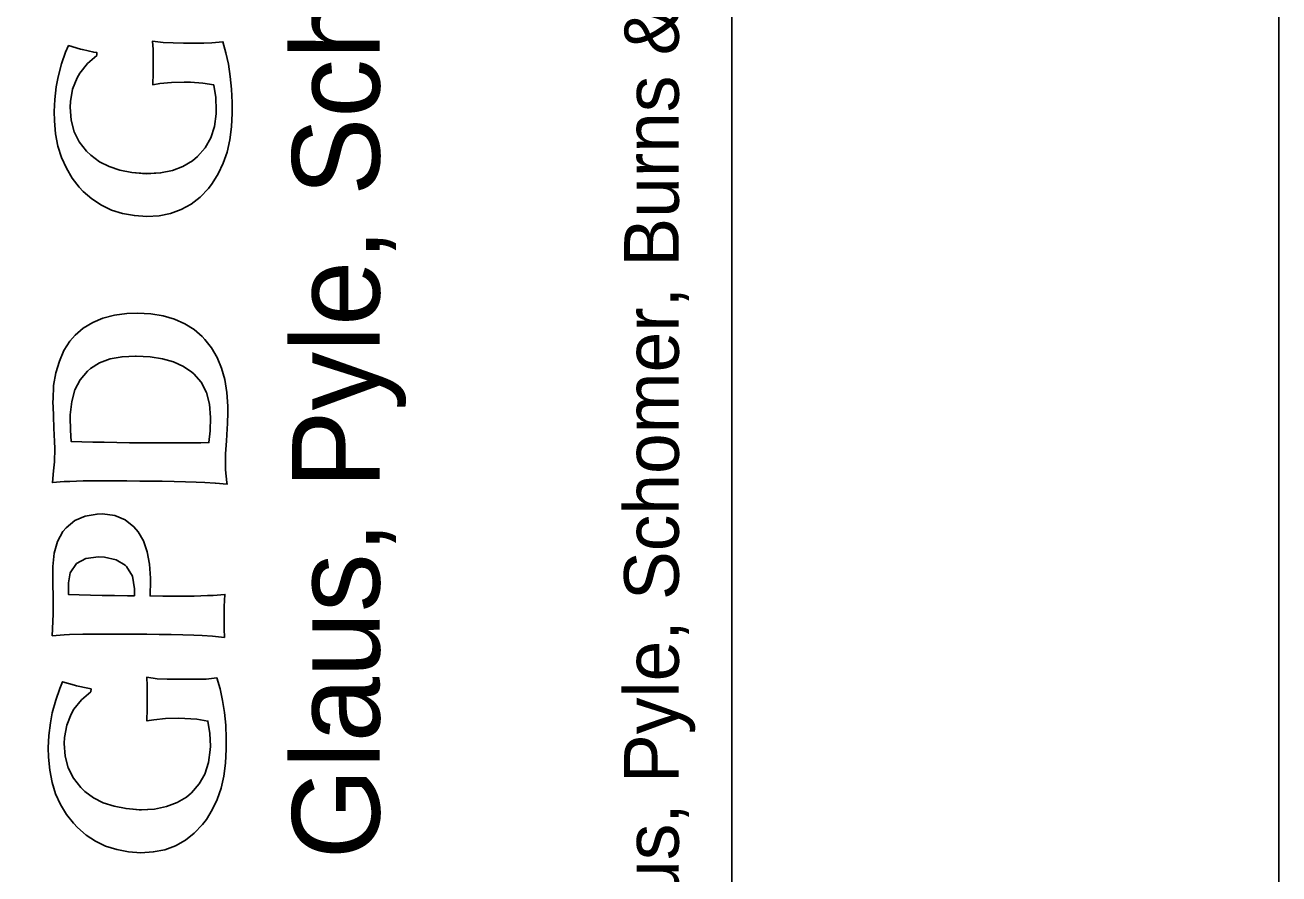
# Model space of a CAD drawing. Extents: x 0 to 34, y 0 to 22.
# Drawn here: x 32.854 to 34, y 19.23 to 20.006 of the extents above; entities that cross this region are included whole.
import ezdxf

# ---------------------------------------------------------------- set-up
doc = ezdxf.new("R2010")
doc.units = 0
for name, color, linetype in [('SH_Border', 7, 'Continuous'), ('SH_Cut_Line', 7, 'Continuous'), ('SH_Data', 7, 'Continuous')]:
    doc.layers.add(name, color=color, linetype=linetype)

msp = doc.modelspace()

# ---------------------------------------------------------------- linework, layer by layer
at = {"layer": 'SH_Border'}
msp.add_lwpolyline([(2, 21.5), (33.5, 21.5), (33.5, 0.5), (2, 0.5)], close=True, dxfattribs=at)
at = {"layer": 'SH_Cut_Line'}
msp.add_lwpolyline([(0, 22), (34, 22), (34, 0), (0, 0)], close=True, dxfattribs=at)
at = {"layer": 'SH_Data'}
for points in [[(32.9515, 19.871), (32.9405, 19.8731), (32.9306, 19.8765), (32.9217, 19.8809), (32.9138, 19.8868), (32.9099, 19.8904), (32.9032, 19.8989), (32.8985, 19.9083), (32.8958, 19.919), (32.895, 19.9306), (32.8952, 19.936), (32.8972, 19.9473), (32.9013, 19.9575), (32.9038, 19.9619), (32.9107, 19.9705), (32.9194, 19.978), (32.9194, 19.9806), (32.9165, 19.981), (32.9062, 19.9833), (32.9043, 19.9839), (32.8935, 19.987), (32.8908, 19.981), (32.8871, 19.9703), (32.884, 19.9585), (32.8823, 19.9493), (32.8809, 19.9378), (32.8804, 19.9268), (32.8806, 19.9181), (32.8816, 19.9063), (32.8838, 19.895), (32.8871, 19.8846), (32.8915, 19.8749), (32.8969, 19.8659), (32.9033, 19.8576), (32.907, 19.8536), (32.9149, 19.8468), (32.9235, 19.8411), (32.9328, 19.8367), (32.9429, 19.8335), (32.9537, 19.8316), (32.9651, 19.8309), (32.9764, 19.8315), (32.9868, 19.8336), (32.9966, 19.8371), (33.0056, 19.8421), (33.0138, 19.8486), (33.0213, 19.8565), (33.0248, 19.8611), (33.0303, 19.8698), (33.0348, 19.8795), (33.0384, 19.8897), (33.0409, 19.9008), (33.0425, 19.9127), (33.0431, 19.9253), (33.043, 19.9351), (33.0425, 19.9472), (33.0413, 19.9589), (33.0397, 19.9699), (33.0374, 19.9805), (33.0346, 19.9906), (33.0246, 19.9894), (33.0172, 19.9892), (33.0042, 19.9892), (32.9985, 19.9892), (32.9891, 19.9894), (32.98, 19.9898), (32.9703, 19.9912), (32.9708, 19.9833), (32.9709, 19.9711), (32.9708, 19.9622), (32.9705, 19.9512), (32.9769, 19.9523), (32.9876, 19.9534), (32.9991, 19.9537), (33.0051, 19.9535), (33.0162, 19.9527), (33.0263, 19.9511), (33.0263, 19.9508), (33.028, 19.9397), (33.0286, 19.928), (33.0285, 19.9247), (33.0269, 19.913), (33.0235, 19.9027), (33.0184, 19.8935), (33.0114, 19.8855), (33.0067, 19.8816), (32.9981, 19.8765), (32.9884, 19.8728), (32.9776, 19.8706), (32.9644, 19.8699), (32.9515, 19.871)], [(33.0303, 19.8698), (33.0348, 19.8795), (33.0384, 19.8897), (33.0409, 19.9008), (33.0425, 19.9127), (33.0431, 19.9253), (33.043, 19.9351), (33.0425, 19.9472), (33.0413, 19.9589), (33.0397, 19.9699), (33.0374, 19.9805), (33.0346, 19.9906), (33.0246, 19.9894), (33.0172, 19.9892), (33.0042, 19.9892), (32.9985, 19.9892), (32.9891, 19.9894), (32.98, 19.9898), (32.9703, 19.9912)], [(32.9703, 19.9912), (32.9708, 19.9833), (32.9709, 19.9711)], [(32.8935, 19.987), (32.8908, 19.981), (32.8871, 19.9703), (32.884, 19.9585), (32.8823, 19.9493), (32.8809, 19.9378), (32.8804, 19.9268)], [(32.895, 19.9306), (32.8952, 19.936), (32.8972, 19.9473), (32.9013, 19.9575), (32.9038, 19.9619), (32.9107, 19.9705), (32.9194, 19.978), (32.9194, 19.9806), (32.9165, 19.981), (32.9062, 19.9833), (32.9043, 19.9839), (32.8935, 19.987)], [(32.895, 19.9306), (32.8952, 19.936), (32.8972, 19.9473), (32.9013, 19.9575), (32.9038, 19.9619), (32.9107, 19.9705), (32.9194, 19.978), (32.9194, 19.9806), (32.9165, 19.981), (32.9062, 19.9833), (32.9043, 19.9839), (32.8935, 19.987)], [(32.9709, 19.9711), (32.9708, 19.9622), (32.9705, 19.9512)], [(32.9705, 19.9512), (32.9769, 19.9523)], [(32.9769, 19.9523), (32.9876, 19.9534), (32.9991, 19.9537), (33.0051, 19.9535), (33.0162, 19.9527), (33.0263, 19.9511), (33.0263, 19.9508), (33.028, 19.9397), (33.0286, 19.928)], [(32.8804, 19.9268), (32.8806, 19.9181), (32.8816, 19.9063), (32.8838, 19.895), (32.8871, 19.8846), (32.8915, 19.8749), (32.8969, 19.8659), (32.9033, 19.8576), (32.907, 19.8536), (32.9149, 19.8468), (32.9235, 19.8411), (32.9328, 19.8367), (32.9429, 19.8335), (32.9537, 19.8316), (32.9651, 19.8309), (32.9764, 19.8315), (32.9868, 19.8336), (32.9966, 19.8371), (33.0056, 19.8421), (33.0138, 19.8486), (33.0213, 19.8565), (33.0248, 19.8611), (33.0303, 19.8698)], [(33.0286, 19.928), (33.0285, 19.9247), (33.0269, 19.913), (33.0235, 19.9027), (33.0184, 19.8935), (33.0114, 19.8855), (33.0067, 19.8816), (32.9981, 19.8765), (32.9884, 19.8728), (32.9776, 19.8706), (32.9656, 19.87), (32.9634, 19.87), (32.9515, 19.871), (32.9405, 19.8731), (32.9306, 19.8765), (32.9217, 19.8809), (32.9138, 19.8868), (32.9099, 19.8904), (32.9032, 19.8989), (32.8985, 19.9083), (32.8958, 19.919), (32.895, 19.9306)], [(32.9904, 19.737), (32.98, 19.7399), (32.9687, 19.7418), (32.9566, 19.7425), (32.9468, 19.7421), (32.9354, 19.7406), (32.925, 19.7379), (32.9156, 19.7339), (32.907, 19.7288), (32.8996, 19.7224), (32.8948, 19.7168), (32.8893, 19.7082), (32.8851, 19.6987), (32.8819, 19.6879), (32.8799, 19.6762), (32.8793, 19.6634), (32.8792, 19.6621), (32.8796, 19.6494), (32.8797, 19.6483), (32.8802, 19.6372), (32.8808, 19.6252), (32.8809, 19.6186), (32.8806, 19.6065), (32.8799, 19.5983), (32.8787, 19.5876), (32.8895, 19.5885), (32.8946, 19.5887), (32.9069, 19.5891), (32.9144, 19.5891), (32.9246, 19.5892), (32.9354, 19.5891), (32.9468, 19.5891), (32.9587, 19.589), (32.9676, 19.5889), (32.979, 19.5888), (32.99, 19.5886), (33.0005, 19.5883), (33.0103, 19.5881), (33.0181, 19.5877), (33.0275, 19.5872), (33.0277, 19.5872), (33.0385, 19.5861), (33.0382, 19.5877), (33.037, 19.5993), (33.037, 19.6008), (33.0371, 19.6122), (33.0371, 19.6138), (33.038, 19.6257), (33.0385, 19.6368), (33.0388, 19.6415), (33.0392, 19.6516), (33.0391, 19.6574), (33.0382, 19.67), (33.0363, 19.6817), (33.0334, 19.6923), (33.0294, 19.702), (33.0243, 19.7107), (33.0182, 19.7185), (33.0158, 19.7211), (33.0082, 19.7276), (32.9997, 19.7328), (32.9904, 19.737)], [(33.0243, 19.7107), (33.0182, 19.7185), (33.0158, 19.7211), (33.0082, 19.7276), (32.9997, 19.7328), (32.9904, 19.737), (32.98, 19.7399), (32.9687, 19.7418), (32.9566, 19.7425), (32.9468, 19.7421), (32.9354, 19.7406), (32.925, 19.7379), (32.9156, 19.7339), (32.907, 19.7288), (32.8996, 19.7224), (32.8948, 19.7168)], [(32.8948, 19.7168), (32.8893, 19.7082), (32.8851, 19.6987), (32.8819, 19.6879)], [(33.0363, 19.6817), (33.0334, 19.6923), (33.0294, 19.702), (33.0243, 19.7107)], [(32.9827, 19.6239), (32.9711, 19.6238), (32.9589, 19.6239), (32.9492, 19.624), (32.9375, 19.6243), (32.9262, 19.6244), (32.9156, 19.6246), (32.9055, 19.6249), (32.8958, 19.6252), (32.8953, 19.6356), (32.8951, 19.6475), (32.8951, 19.6494), (32.8964, 19.6616), (32.8994, 19.6724), (32.9041, 19.6816), (32.9107, 19.6893), (32.9137, 19.6919), (32.9219, 19.6969), (32.9314, 19.7006), (32.9424, 19.7026), (32.9551, 19.7032), (32.9681, 19.7025), (32.9795, 19.7007), (32.9896, 19.6979), (32.9985, 19.6937), (33.0061, 19.6886), (33.0079, 19.687), (33.0147, 19.6793), (33.0195, 19.67), (33.0223, 19.6593), (33.0232, 19.6471), (33.0229, 19.635), (33.0219, 19.6241), (33.0144, 19.624), (33.0045, 19.6238), (32.9938, 19.6238), (32.9827, 19.6239)], [(32.8951, 19.6475), (32.8951, 19.6494), (32.8964, 19.6616), (32.8994, 19.6724), (32.9041, 19.6816), (32.9107, 19.6893), (32.9137, 19.6919), (32.9219, 19.6969), (32.9314, 19.7006), (32.9424, 19.7026), (32.9548, 19.7032), (32.9554, 19.7032), (32.9681, 19.7025), (32.9795, 19.7007), (32.9896, 19.6979), (32.9985, 19.6937), (33.0061, 19.6886), (33.0079, 19.687), (33.0147, 19.6793), (33.0195, 19.67), (33.0223, 19.6593), (33.0232, 19.6472), (33.0232, 19.647)], [(32.8819, 19.6879), (32.8799, 19.6762), (32.8793, 19.6634)], [(33.0371, 19.6122), (33.0371, 19.6138), (33.038, 19.6257), (33.0385, 19.6368), (33.0388, 19.6415), (33.0392, 19.6516), (33.0391, 19.6574), (33.0382, 19.67), (33.0363, 19.6817)], [(33.0371, 19.6122), (33.0371, 19.6138), (33.038, 19.6257), (33.0385, 19.6368), (33.0388, 19.6415), (33.0392, 19.6516), (33.0391, 19.6574), (33.0382, 19.67), (33.0363, 19.6817)], [(32.8793, 19.6634), (32.8792, 19.6621), (32.8796, 19.6494), (32.8797, 19.6483), (32.8802, 19.6372), (32.8808, 19.6252), (32.8809, 19.6186)], [(33.0232, 19.647), (33.0229, 19.635), (33.0219, 19.6241), (33.0144, 19.624), (33.0045, 19.6238), (32.9938, 19.6238), (32.9827, 19.6239), (32.9711, 19.6238), (32.9589, 19.6239), (32.9492, 19.624), (32.9375, 19.6243), (32.9262, 19.6244), (32.9156, 19.6246), (32.9055, 19.6249), (32.8958, 19.6252), (32.8953, 19.6356), (32.8951, 19.6475)], [(32.8809, 19.6186), (32.8806, 19.6065), (32.8799, 19.5983), (32.8787, 19.5876)], [(32.8787, 19.5876), (32.8895, 19.5885), (32.8946, 19.5887), (32.9069, 19.5891), (32.9144, 19.5891), (32.9246, 19.5892), (32.9354, 19.5891), (32.9468, 19.5891), (32.9587, 19.589), (32.9676, 19.5889), (32.979, 19.5888), (32.99, 19.5886), (33.0005, 19.5883), (33.0103, 19.5881), (33.0181, 19.5877), (33.0275, 19.5872), (33.0277, 19.5872), (33.0385, 19.5861), (33.0382, 19.5877), (33.037, 19.5993), (33.037, 19.6008), (33.0371, 19.6122)], [(32.9908, 19.4838), (32.9796, 19.4839), (32.968, 19.484), (32.9684, 19.4981), (32.9684, 19.5001), (32.9676, 19.513), (32.9654, 19.5243), (32.9619, 19.5343), (32.9571, 19.5427), (32.9532, 19.5472), (32.9452, 19.5536), (32.9357, 19.5575), (32.9246, 19.5589), (32.9196, 19.5588), (32.9086, 19.5569), (32.8992, 19.5528), (32.8913, 19.5463), (32.8884, 19.5429), (32.8833, 19.5338), (32.8803, 19.523), (32.8791, 19.5108), (32.8793, 19.4672), (32.8786, 19.4476), (32.8894, 19.4485), (32.8944, 19.4487), (32.9067, 19.449), (32.9131, 19.4491), (32.9233, 19.4492), (32.9341, 19.4491), (32.9456, 19.4491), (32.9574, 19.449), (32.965, 19.4489), (32.9764, 19.4488), (32.9874, 19.4486), (32.9979, 19.4483), (33.0079, 19.4481), (33.0157, 19.4477), (33.0252, 19.4472), (33.036, 19.4461), (33.0358, 19.4538), (33.0358, 19.4659), (33.0359, 19.4744), (33.0364, 19.4854), (33.0256, 19.4845), (33.0205, 19.4844), (33.0082, 19.4839), (33.0013, 19.4838), (32.9908, 19.4838)], [(32.9571, 19.5427), (32.9532, 19.5472), (32.9452, 19.5536), (32.9357, 19.5575), (32.9246, 19.5589), (32.9196, 19.5588), (32.9086, 19.5569), (32.8992, 19.5528), (32.8913, 19.5463)], [(32.8913, 19.5463), (32.8884, 19.5429), (32.8833, 19.5338), (32.8803, 19.523)], [(32.9676, 19.513), (32.9654, 19.5243), (32.9619, 19.5343), (32.9571, 19.5427)], [(32.8803, 19.523), (32.8791, 19.5108)], [(32.8791, 19.5108), (32.8793, 19.4672)], [(32.9538, 19.484), (32.9473, 19.484), (32.9355, 19.4843), (32.9242, 19.4845), (32.9135, 19.4848), (32.9033, 19.485), (32.8936, 19.4852), (32.8936, 19.4959), (32.895, 19.505), (32.9007, 19.5136), (32.9092, 19.5183), (32.9208, 19.5198), (32.9264, 19.5194), (32.9371, 19.5169), (32.9453, 19.5121), (32.9466, 19.5109), (32.952, 19.5022), (32.9537, 19.4906), (32.9538, 19.484)], [(32.8936, 19.4959), (32.895, 19.505), (32.9007, 19.5136), (32.9092, 19.5183), (32.9208, 19.5198), (32.9264, 19.5194), (32.9371, 19.5169), (32.9453, 19.5121), (32.9466, 19.5109), (32.952, 19.5022), (32.9537, 19.4906), (32.9538, 19.484)], [(32.968, 19.484), (32.9684, 19.4981), (32.9684, 19.5001), (32.9676, 19.513)], [(32.968, 19.484), (32.9684, 19.4981), (32.9684, 19.5001), (32.9676, 19.513)], [(32.9538, 19.484), (32.9473, 19.484), (32.9355, 19.4843), (32.9242, 19.4845), (32.9135, 19.4848), (32.9033, 19.485), (32.8936, 19.4852), (32.8936, 19.4959)], [(33.0358, 19.4659), (33.0359, 19.4744), (33.0364, 19.4854), (33.0364, 19.4854), (33.0256, 19.4845), (33.0205, 19.4844), (33.0082, 19.4839), (33.0013, 19.4838), (32.9908, 19.4838), (32.9796, 19.4839), (32.968, 19.484)], [(32.8793, 19.4672), (32.8786, 19.4476)], [(33.0252, 19.4472), (33.036, 19.4461), (33.0358, 19.4538), (33.0358, 19.4659)], [(32.8786, 19.4476), (32.8894, 19.4485), (32.8944, 19.4487), (32.9067, 19.449), (32.9131, 19.4491), (32.9233, 19.4492), (32.9341, 19.4491), (32.9456, 19.4491), (32.9574, 19.449), (32.965, 19.4489), (32.9764, 19.4488), (32.9874, 19.4486), (32.9979, 19.4483), (33.0079, 19.4481), (33.0157, 19.4477), (33.0252, 19.4472), (33.0252, 19.4472)], [(32.9252, 19.295), (32.9163, 19.2995), (32.9084, 19.3053), (32.9046, 19.309), (32.8979, 19.3175), (32.8932, 19.3269), (32.8904, 19.3375), (32.8896, 19.3492), (32.8898, 19.3546), (32.8918, 19.3659), (32.8959, 19.376), (32.8984, 19.3805), (32.9053, 19.389), (32.914, 19.3964), (32.9141, 19.399), (32.9112, 19.3996), (32.9008, 19.4019), (32.8989, 19.4025), (32.8881, 19.4056), (32.8855, 19.3994), (32.8818, 19.3888), (32.8786, 19.377), (32.877, 19.3679), (32.8756, 19.3564), (32.875, 19.3453), (32.8752, 19.3367), (32.8763, 19.3247), (32.8785, 19.3136), (32.8817, 19.303), (32.8861, 19.2933), (32.8915, 19.2843), (32.8979, 19.2762), (32.9016, 19.2723), (32.9095, 19.2654), (32.9181, 19.2597), (32.9274, 19.2553), (32.9375, 19.2522), (32.9483, 19.2502), (32.9597, 19.2493), (32.971, 19.25), (32.9814, 19.252), (32.9913, 19.2557), (33.0003, 19.2607), (33.0084, 19.2671), (33.016, 19.2751), (33.0195, 19.2797), (33.0249, 19.2884), (33.0295, 19.2979), (33.033, 19.3083), (33.0356, 19.3194), (33.0371, 19.3312), (33.0377, 19.3439), (33.0376, 19.3536), (33.0372, 19.3658), (33.036, 19.3774), (33.0343, 19.3885), (33.032, 19.3991), (33.0292, 19.4091), (33.0192, 19.4079), (33.0119, 19.4078), (32.9989, 19.4078), (32.9931, 19.4078), (32.9837, 19.4079), (32.9746, 19.4083), (32.965, 19.4097), (32.9655, 19.4019), (32.9655, 19.3897), (32.9654, 19.3808), (32.9652, 19.3698), (32.9715, 19.3709), (32.9822, 19.372), (32.9938, 19.3723), (32.9997, 19.3721), (33.0108, 19.3713), (33.0209, 19.3696), (33.0209, 19.3695), (33.0227, 19.3582), (33.0233, 19.3466), (33.0231, 19.3432), (33.0215, 19.3316), (33.0181, 19.3211), (33.013, 19.3121), (33.006, 19.3041), (33.0013, 19.3002), (32.9928, 19.2951), (32.9831, 19.2914), (32.9722, 19.2892), (32.9591, 19.2885), (32.9461, 19.2896), (32.9351, 19.2917), (32.9252, 19.295)], [(33.0249, 19.2884), (33.0295, 19.2979), (33.033, 19.3083), (33.0356, 19.3194), (33.0371, 19.3312), (33.0377, 19.3439), (33.0376, 19.3536), (33.0372, 19.3658), (33.036, 19.3774), (33.0343, 19.3885), (33.032, 19.3991), (33.0292, 19.4091), (33.0192, 19.4079), (33.0119, 19.4078), (32.9989, 19.4078), (32.9931, 19.4078), (32.9837, 19.4079), (32.9746, 19.4083), (32.965, 19.4097)], [(32.965, 19.4097), (32.9655, 19.4019), (32.9655, 19.3897)], [(32.8881, 19.4056), (32.8855, 19.3994), (32.8818, 19.3888), (32.8786, 19.377), (32.877, 19.3679), (32.8756, 19.3564), (32.875, 19.3453)], [(32.8896, 19.3492), (32.8898, 19.3546), (32.8918, 19.3659), (32.8959, 19.376), (32.8984, 19.3805), (32.9053, 19.389), (32.914, 19.3964), (32.9141, 19.399), (32.9112, 19.3996), (32.9008, 19.4019), (32.8989, 19.4025), (32.8881, 19.4056)], [(32.8896, 19.3492), (32.8898, 19.3546), (32.8918, 19.3659), (32.8959, 19.376), (32.8984, 19.3805), (32.9053, 19.389), (32.914, 19.3964), (32.9141, 19.399), (32.9112, 19.3996), (32.9008, 19.4019), (32.8989, 19.4025), (32.8881, 19.4056)], [(32.9655, 19.3897), (32.9654, 19.3808), (32.9652, 19.3698)], [(32.9715, 19.3709), (32.9822, 19.372), (32.9938, 19.3723), (32.9997, 19.3721), (33.0108, 19.3713), (33.0209, 19.3696), (33.0209, 19.3695), (33.0227, 19.3582), (33.0233, 19.3466)], [(32.9652, 19.3698), (32.9715, 19.3709)], [(33.0233, 19.3466), (33.0231, 19.3432), (33.0215, 19.3316), (33.0181, 19.3211), (33.013, 19.3121), (33.006, 19.3041), (33.0013, 19.3002), (32.9928, 19.2951), (32.9831, 19.2914), (32.9722, 19.2892), (32.9602, 19.2886), (32.9581, 19.2886), (32.9461, 19.2896), (32.9351, 19.2917), (32.9252, 19.295), (32.9163, 19.2995), (32.9084, 19.3053), (32.9046, 19.309), (32.8979, 19.3175), (32.8932, 19.3269), (32.8904, 19.3375), (32.8896, 19.3492)], [(32.875, 19.3453), (32.8752, 19.3367), (32.8763, 19.3247), (32.8785, 19.3136), (32.8817, 19.303), (32.8861, 19.2933), (32.8915, 19.2843), (32.8979, 19.2762), (32.9016, 19.2723), (32.9095, 19.2654), (32.9181, 19.2597), (32.9274, 19.2553), (32.9375, 19.2522), (32.9483, 19.2502), (32.9597, 19.2493), (32.971, 19.25), (32.9814, 19.252), (32.9913, 19.2557), (33.0003, 19.2607), (33.0084, 19.2671), (33.016, 19.2751), (33.0195, 19.2797), (33.0249, 19.2884)]]:
    msp.add_lwpolyline(points, dxfattribs=at)

# ---------------------------------------------------------------- texts
for s, height, p in [('Glaus, Pyle, Schomer, Burns & DeHaven, Inc.', 0.08, (33.1779, 19.2433)), ('Copyright: Glaus, Pyle, Schomer, Burns & Dehaven, Inc. 2023', 0.05, (33.4514, 18.7779))]:
    msp.add_text(s, height=height, rotation=90, dxfattribs=at).set_placement(p)

doc.saveas('drawing.dxf')
